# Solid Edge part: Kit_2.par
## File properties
Author: bmolnar
Last saved by: bmolnar
Revision: 77
Sűrűség: 0,000 kg/m^3
Pontosság: 0,990
Username: bmolnar
Dokumentum tartalom típus: 0
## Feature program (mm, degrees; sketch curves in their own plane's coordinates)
base feature "unnamed BaseFeature 1"
thread "unnamed Thread 1"
sketch for "unnamed Hole 1" plane through (-23.25, -23.25, 90) normal (0, 0, 1) x-axis (0, 1, 0)
  hole centre (0, 0) bore radius 3.3235
hole "unnamed Hole 1" through
sketch for "unnamed Hole 2" plane through (-23.25, -23.25, 90) normal (0, 0, 1) x-axis (0, 1, 0)
  hole centre (46.5, 0) bore radius 3.3235
hole "unnamed Hole 2" through
sketch for "unnamed Hole 3" plane through (-23.25, -23.25, 90) normal (0, 0, 1) x-axis (0, 1, 0)
  hole centre (0, -46.5) bore radius 3.3235
hole "unnamed Hole 3" through
sketch for "unnamed Hole 4" plane through (-23.25, -23.25, 90) normal (0, 0, 1) x-axis (0, 1, 0)
  hole centre (46.5, -46.5) bore radius 3.3235
hole "unnamed Hole 4" through
pattern "unnamed Pattern 1" of "unnamed Hole 1", "unnamed Hole 2", "unnamed Hole 3", "unnamed Hole 4"
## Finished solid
Body 1: solid body, 320 faces, 747 edges, 446 vertices, 4 internal voids.
  Faces by surface: plane 141, cylinder 83, swept 53, torus 22, cone 20, spline 1
  Edges by curve: line 413, circle 177, spline 118, ellipse 28, curve on surface 10, intersection 1
Bounding box of the edges (mm; curved faces can reach further): 65.500 x 65.500 x 14.500, from (-32.75, -32.75, 80.5) to (32.75, 32.75, 95).
Cylindrical faces by radius (mm): R0.2 x40, R0.201 x2, R0.2012 x2, R1.75 x1, R2.5402 x12, R2.6 x4, R3.3235 x4, R3.75 x4, R3.85 x4, R4.283 x1, R5.25 x4, R8.27 x1, R8.85 x1, R9 x1, R10.25 x1, R15.5811 x1
Conical faces (half-angle, radius in mm at the cone's reference point): 0.5 deg R6.5 x2, 0.5 deg R8 x4, 7 deg R9.5925 x1, 14 deg R8.135 x1, 14 deg R8.4811 x1, 17 deg R8.135 x1, 23 deg R8.829 x1, 42.5 deg R8.1233 x1, 45 deg R3.6735 x4, 45 deg R9 x1, 84 deg R8.4608 x1, 85 deg R9.9463 x1, 87 deg R8.1765 x1
Toroidal faces (ring radius, tube radius in mm): R2.9402 r0.4 x12, R3.55 r0.2 x8, R8.8057 r0.2025 x1, R9.2522 r0.2925 x1
Planar faces by outward normal: +x 12, +y 12, +z 24, -x 14, -y 12, -z 1, oblique 66
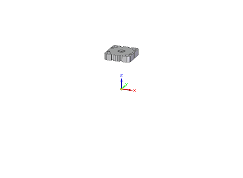
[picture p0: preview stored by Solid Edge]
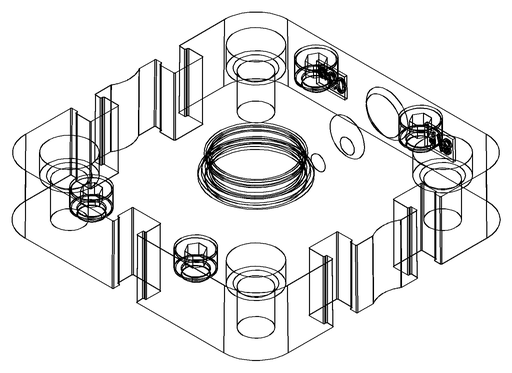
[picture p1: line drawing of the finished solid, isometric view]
